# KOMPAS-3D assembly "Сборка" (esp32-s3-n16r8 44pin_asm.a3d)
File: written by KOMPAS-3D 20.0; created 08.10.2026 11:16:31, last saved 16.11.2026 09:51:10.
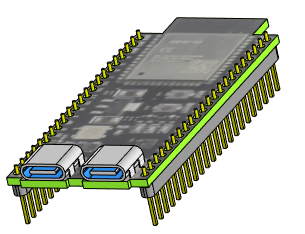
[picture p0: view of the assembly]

Document properties: Полное имя файла: D:\RicWork\Project-EPS32\box_compas\esp32\esp32-s3-n16r8 44pin_asm.a3d

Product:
- Part/product: Сборка
    Масса: 0.027715
  - Component [detail]: Деталь  | Масса: 0.019451; source file: esp32-s3-n16r8 44pin.m3d
  - Component [detail]: Деталь  | qty 2  | Масса: 0.00285166; source file: ..\разъемы\pls_22.m3d
  - Component [detail]: Деталь  | qty 2  | Масса: 0.00128034; source file: ..\разъемы\type-c female.m3d

Referenced files in D:\RicWork\Project-EPS32\box_compas\разъемы\: pls_22.m3d, type-c female.m3d
Referenced files in D:\RicWork\Project-EPS32\box_compas\esp32\: esp32-s3-n16r8 44pin.m3d
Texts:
  Деталь (1)
  Деталь (2)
